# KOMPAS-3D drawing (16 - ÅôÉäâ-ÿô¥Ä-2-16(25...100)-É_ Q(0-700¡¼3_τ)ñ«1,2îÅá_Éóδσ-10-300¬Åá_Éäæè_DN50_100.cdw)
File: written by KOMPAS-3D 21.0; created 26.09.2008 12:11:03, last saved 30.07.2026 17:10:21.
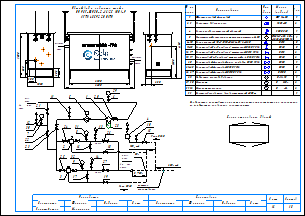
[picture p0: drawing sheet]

Sheets 1-2: A3, landscape

Document properties: Наименование: Макро:21; Автор: RaskoAdmin; Форматы листов документа: 2xA3; Полное имя файла: \\ur38nt01\Departments\КТО\КБ ПУРДГ\Заявки\Прайс-лист на типовые шкафы ГРПШ\ПУРДГ_стандарт_30_04_2026\ПУРДГ с РДСК\ПУРДГ-ШУЭО-2-16(25...100)-Р_ Q(0-700нм3_ч)до1,2МПа_Рвых-10-300кПа_РДСК_DN50_100.cdw

Title block, sheet 1: Наименование: Пункт учета газа / ПУГ-Ш-400-Р / ЛГТИ.485922.001ТУ; designation: ЛГТИ.03.4411141; sheet number: 1; Количество листов документа: 2; organisation: ООО "ЭЛЬСТЕР Газэлектроника"; Форматы листов документа: A3; stored path: C:\Рабочие документы\Компас\ПУГ\Схема.cdw; Разработал: Устинов; Проверил: Кошкин; Утвердил: Кошкин
Title block, sheet 2: sheet number: 2; stored path: D:\Рабочие документы\Заявки\ПУРДГ\ПУРДГ-ШУЭО-2-100-Р 4411220.cdw; designation, second copy: ЛГТИ.03.4411141-

Views: Вид 1, Вид 2
Referenced files: wcvoit.frw
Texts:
  Normal
  № на
  схеме
  Усл.
  обозн.
  Марка
  (модель)
  Кол.
  Фильтр газовый фланцевый
  ФГ 16-50
  Регулятор давления газа
  РДСК-50
  Клапан предохранительный сбросной
  КПС DN20
  Измерительный комплекс с ротационным счетчиком Ду50
  СГ-ЭК-Р-(0,2...2,0)-
  Кран кнопочный VE-РАСКО-НЗ-1,6-G1/2-М20
  DN15
  Кран шаровой "под приварку" штуцерный DN20 PN16
  DN20
  Кран шаровой "под приварку" штуцерный DN15 PN16
  Кран шаровой "под приварку" штуцерный п/п DN20 PN16
  Кран шаровой фланцевый с мех. приводом DN50 PN16
  Кран шаровой фланцевый DN50 PN16
  Кран шаровой фланцевый DN100 PN16
  DN50
  DN100
  Индикатор перепада давления
  Манометр
  Манометр-напоромер
  Электрообогреватель взрывозащищенный 400Вт
  Delta 15
  0...     МПа
  0...     кПа
  Общий вид и габариты шкафа
  ПУРДГ-ШУЭО-2-16(25...100)-Р
  Выход газа
  Вход газа
  logo-rasko-ge.png
  DN 1
  местное
  сопротивление
  Римп DN20
  Выход
  газа
  Р=     кПа
  Вход
  Р=       МПа
  PDI
  Схема открывания дверей
  Предприятие изготовитель может заменять комплектующие на аналогичные,
  не ухудшающие заявленных характеристик.
  Должность
  Конструктор
  Фамилия
  Подпись
  Дата
  Согласовано
  Максимкин
  Лист
  Листов
  POLYLINE_STYLE_0.18_RGB_0_0_0
  POLYLINE_STYLE_0.50_RGB_0_0_0
  POLYLINE_STYLE_0.34_RGB_0_0_0
  PHANTOM_RGB_0_0_0_SC_1_THICK_0.18
  K5LT_THIN_RGB_0_0_0_THICK_0.18
  K5LT32769_RGB_0_0_0_THICK_0.18
  K5LT12_RGB_0_0_0_SC_1_THICK_0.18
  K5LT_DASHED_RGB_0_0_0_SC_1_THICK_0.18
  ACISOTGL_RGB_0_0_0_SC_0.8_THICK_0.25
  CONTINUOUS_RGB_0_127_31_THICK_0.3
  CONTINUOUS_RGB_0_0_255_THICK_0.35
  CONTINUOUS_RGB_255_0_0_THICK_0.35
  POLYLINE_STYLE_0.25_RGB_0_0_0
  CONTINUOUS_RGB_0_0_0_THICK_0.5
  POLYLINE_STYLE_0.35_RGB_0_0_255
  CONTINUOUS_RGB_0_0_0_THICK_0.4
  CONTINUOUS_RGB_0_0_0_THICK_0.35
  НЕВИДИМАЯ_RGB_0_0_0_SC_0.3_THICK_0.25
  СONTINUOUS_RGB_0_0_0_THICK_0.25
  ОСЕВАЯ2_RGB_248_153_30_SC_0.3_THICK_0.25
  Без оформления
Dimensions and other numbers on the sheet: 1; 2, 3; 2; 4; 5; 6-10; 11-15; 16, 17; 18, 19; 20; 21-25; 26, 27; 28; 29, 30; 31, 32; 33; 1500; 250; 300; 1050; 550; 305; 2300; 4130; 2000; 2600; 5,,,7DN 1; 7; 30; 12; 21; 22; 23; 11; 6; 29; 24; 31; 8; 16; 13; 26; 18; 10; 15; 25; 32; 9; 3; 17; 14; 27; 19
